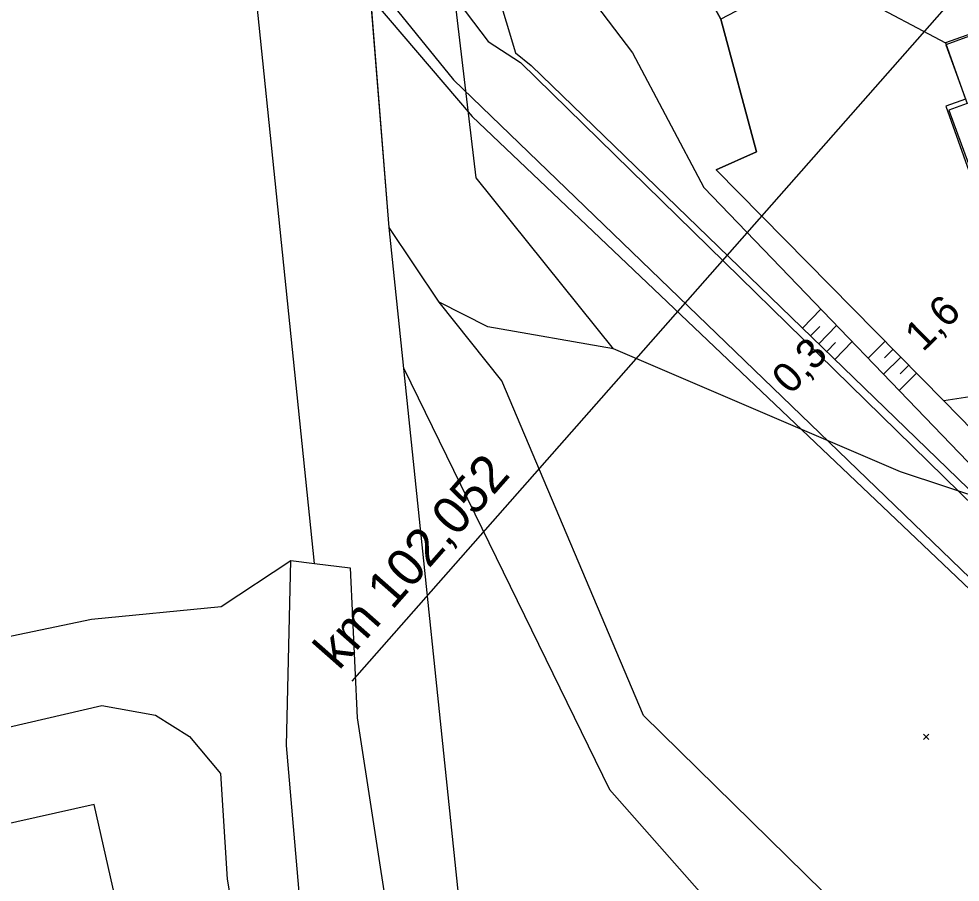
# Model space of a CAD drawing. Extents: x -800194 to -799078, y -1007177 to -1006597.
# Drawn here: x -799850.9 to -799787.9, y -1007068 to -1007010.2 of the extents above; entities that cross this region are included whole.
import ezdxf

# ---------------------------------------------------------------- set-up
doc = ezdxf.new("R2010")
doc.units = 0
for name, color, linetype in [('Vrstva 13', 7, 'Continuous'), ('Vrstva 17', 7, 'Continuous'), ('Vrstva 23', 7, 'Continuous'), ('Vrstva 3', 7, 'Continuous'), ('Vrstva 48', 7, 'Continuous'), ('Vrstva 49', 7, 'Continuous'), ('Vrstva 51', 7, 'Continuous'), ('Vrstva 53', 7, 'Continuous'), ('Vrstva 55', 7, 'Continuous')]:
    doc.layers.add(name, color=color, linetype=linetype)

msp = doc.modelspace()

# ---------------------------------------------------------------- linework, layer by layer
at = {"layer": 'Vrstva 13'}
msp.add_lwpolyline([(-799805.067, -1007021.457), (-799784.005, -1007043.381), (-799779.029, -1007045.556), (-799742.637, -1007054.554), (-799725.892, -1007059.592)], dxfattribs=at)
at = {"layer": 'Vrstva 17'}
msp.add_line((-799797.881, -1007007.005), (-799788.905, -1007011.78), dxfattribs=at)
for points in [[(-799828.95, -1007006.881), (-799820.579, -1007016.712), (-799786.808, -1007048.821), (-799777.641, -1007052.247), (-799745.452, -1007060.292), (-799727.709, -1007066.187)], [(-799744.108, -1007040.301), (-799744.795, -1007042.69), (-799746.422, -1007047.465), (-799747.487, -1007048.694), (-799771.226, -1007044.934), (-799785.53, -1007035.198), (-799789.014, -1007035.746), (-799804.246, -1007020.27), (-799801.55, -1007019.072), (-799803.933, -1007010.185)]]:
    msp.add_lwpolyline(points, dxfattribs=at)
at = {"layer": 'Vrstva 23'}
for points in [[(-799797.881, -1007007.005), (-799803.933, -1007010.185), (-799810.13, -1006998.908), (-799804.077, -1006995.693), (-799797.881, -1007007.005)], [(-799785.137, -1007010.437), (-799788.905, -1007011.78), (-799787.561, -1007015.548), (-799788.88, -1007016.018), (-799786.155, -1007023.66), (-799781.069, -1007021.847), (-799785.137, -1007010.437)]]:
    msp.add_lwpolyline(points, dxfattribs=at)
at = {"layer": 'Vrstva 3'}
msp.add_line((-799769.882, -1006987.807), (-799828.64, -1007054.5), dxfattribs=at)
at = {"layer": 'Vrstva 48'}
for p, q in [((-799798.468, -1007030.877), (-799797.238, -1007029.606)), ((-799797.93, -1007031.399), (-799797.324, -1007030.773)), ((-799797.391, -1007031.92), (-799796.198, -1007030.689)), ((-799796.852, -1007032.442), (-799796.265, -1007031.836)), ((-799796.313, -1007032.964), (-799795.158, -1007031.771)), ((-799792.942, -1007031.756), (-799794.089, -1007032.885)), ((-799792.415, -1007032.29), (-799792.992, -1007032.858)), ((-799791.889, -1007032.825), (-799793.049, -1007033.966)), ((-799791.363, -1007033.359), (-799791.947, -1007033.933)), ((-799790.837, -1007033.894), (-799792.01, -1007035.048))]:
    msp.add_line(p, q, dxfattribs=at)
at = {"layer": 'Vrstva 49'}
for p, q in [((-799790.372, -1007058.057), (-799790.018, -1007058.411)), ((-799790.372, -1007058.411), (-799790.018, -1007058.057))]:
    msp.add_line(p, q, dxfattribs=at)
for points in [[(-799823.433, -1006985.376), (-799817.838, -1006990.049), (-799815.5, -1006993.967), (-799810.13, -1006998.908), (-799803.933, -1007010.185), (-799801.55, -1007019.072), (-799804.246, -1007020.27), (-799789.014, -1007035.746), (-799784.101, -1007040.767), (-799778.537, -1007044.165), (-799742.314, -1007053.114), (-799725.901, -1007057.997)], [(-799823.433, -1006985.376), (-799822.824, -1006995.382), (-799809.853, -1007012.441), (-799805.067, -1007021.457), (-799784.005, -1007043.381), (-799779.029, -1007045.556), (-799742.637, -1007054.554), (-799725.892, -1007059.592)], [(-799822.824, -1006995.382), (-799817.689, -1007012.452), (-799816.629, -1007013.288), (-799784.593, -1007044.315), (-799779.066, -1007046.684), (-799743.002, -1007056.174), (-799726.202, -1007060.605)]]:
    msp.add_lwpolyline(points, dxfattribs=at)
at = {"layer": 'Vrstva 51'}
for points in [[(-799817.051, -1006918.973), (-799812.091, -1006931.542), (-799815.665, -1006943.128), (-799826.019, -1006959.481), (-799831.215, -1006965.513), (-799832.478, -1006972.309), (-799831.126, -1006986.858), (-799828.082, -1006983.271), (-799821.896, -1006976.034), (-799813.152, -1006974.923), (-799805.94, -1006982.791), (-799808.362, -1006984.771), (-799815.088, -1006977.554), (-799820.319, -1006978.428), (-799823.433, -1006985.376), (-799830.084, -1006997.726), (-799819.519, -1007011.695), (-799817.354, -1007013.08), (-799784.788, -1007044.956), (-799778.171, -1007047.694), (-799743.858, -1007056.783), (-799726.629, -1007061.89)], [(-799842.202, -1006982.511), (-799833.072, -1007000.361), (-799821.843, -1007014.249), (-799786.621, -1007048.212), (-799778.768, -1007050.961), (-799745.381, -1007058.848), (-799727.01, -1007064.42)]]:
    msp.add_lwpolyline(points, dxfattribs=at)
at = {"layer": 'Vrstva 53'}
msp.add_lwpolyline([(-799673.33, -1007118.14), (-799714.71, -1007110.97), (-799718.21, -1007083.69), (-799729.93, -1007087.54), (-799766.47, -1007095.84), (-799767.73, -1007094.8), (-799769.22, -1007093.56), (-799785.06, -1007080.42), (-799809.11, -1007056.81), (-799818.59, -1007034.4), (-799822.79, -1007029.13), (-799826.14, -1007024.13), (-799830.75, -1006966.73), (-799839.73, -1006961.33), (-799877.87, -1006942.17), (-799936.47, -1006903.99), (-799954.76, -1006895.45), (-799964.79, -1006890.84)], dxfattribs=at)
at = {"layer": 'Vrstva 55'}
for p, q in [((-799826.14, -1007024.13), (-799830.75, -1006966.73)), ((-799825.16, -1007033.58), (-799826.14, -1007024.13)), ((-799822.79, -1007029.13), (-799826.14, -1007024.13)), ((-799818.85, -1007094.38), (-799825.16, -1007033.58)), ((-799832.71, -1007046.42), (-799831.14, -1007046.62)), ((-799854.29, -1007052.07), (-799846.07, -1007050.35))]:
    msp.add_line(p, q, dxfattribs=at)
for points in [[(-799811.13, -1007032.26), (-799820.31, -1007020.81), (-799827.08, -1006963.79), (-799830.75, -1006966.73)], [(-799831.14, -1007046.62), (-799837.54, -1006984.31), (-799843.2, -1006977.69), (-799849.98, -1006977.29), (-799866.6, -1006981.12)], [(-799788.68, -1007016.29), (-799786.88, -1007021.22), (-799785.99, -1007023.53), (-799780.99, -1007021.72), (-799781.84, -1007019.38), (-799785.05, -1007010.5), (-799788.88, -1007011.9), (-799787.45, -1007015.84), (-799788.68, -1007016.29)], [(-799769.22, -1007093.56), (-799785.06, -1007080.42), (-799809.11, -1007056.81), (-799818.59, -1007034.4), (-799822.79, -1007029.13)], [(-799811.13, -1007032.26), (-799819.54, -1007030.79), (-799822.79, -1007029.13)], [(-799727.16, -1007050.52), (-799734.57, -1007049.13), (-799749.18, -1007049.49), (-799773.9, -1007046.46), (-799791.91, -1007040.49), (-799811.13, -1007032.26)], [(-799825.16, -1007033.58), (-799811.39, -1007061.77), (-799794.49, -1007080.93), (-799774.66, -1007093.65)], [(-799846.07, -1007050.35), (-799837.39, -1007049.52), (-799832.71, -1007046.42)], [(-799823.03, -1007089.38), (-799825.77, -1007089.63), (-799827.26, -1007088.72), (-799830.02, -1007078.85), (-799832.03, -1007070.18), (-799833.02, -1007058.82), (-799832.71, -1007046.42)], [(-799831.14, -1007046.62), (-799828.75, -1007046.93), (-799828.27, -1007056.97), (-799826.13, -1007070.87), (-799825.16, -1007076.77), (-799823.03, -1007089.38)], [(-799858.84, -1007065.67), (-799858.76, -1007060.77), (-799858.72, -1007059.86), (-799857.59, -1007058.97), (-799845.38, -1007056.13), (-799841.77, -1007056.79), (-799839.5, -1007058.21), (-799837.43, -1007060.68), (-799836.99, -1007067.77), (-799836.14, -1007072.71), (-799834.61, -1007079.6), (-799832.83, -1007084.94), (-799830.58, -1007092.52), (-799828.9, -1007096.44), (-799827.32, -1007101.2), (-799825.89, -1007106.02), (-799824.52, -1007111.92), (-799824.25, -1007121.19), (-799824.17, -1007122.98), (-799825.87, -1007124.09), (-799830.82, -1007128.75)], [(-799846.34, -1007114.47), (-799834.79, -1007111.87), (-799845.89, -1007062.76), (-799858.84, -1007065.67)]]:
    msp.add_lwpolyline(points, dxfattribs=at)

# ---------------------------------------------------------------- texts
at = {"layer": 'Vrstva 3'}
msp.add_text('km 102,052', height=2.5, rotation=48.61928, dxfattribs=at).set_placement((-799829.503, -1007053.837))
at = {"layer": 'Vrstva 48'}
for s, rotation, p in [('1,6', 44.54475, (-799790.416, -1007032.518)), ('0,3', 45.91665, (-799799.272, -1007035.389))]:
    msp.add_text(s, height=2, rotation=rotation, dxfattribs=at).set_placement(p)

doc.saveas('drawing.dxf')
